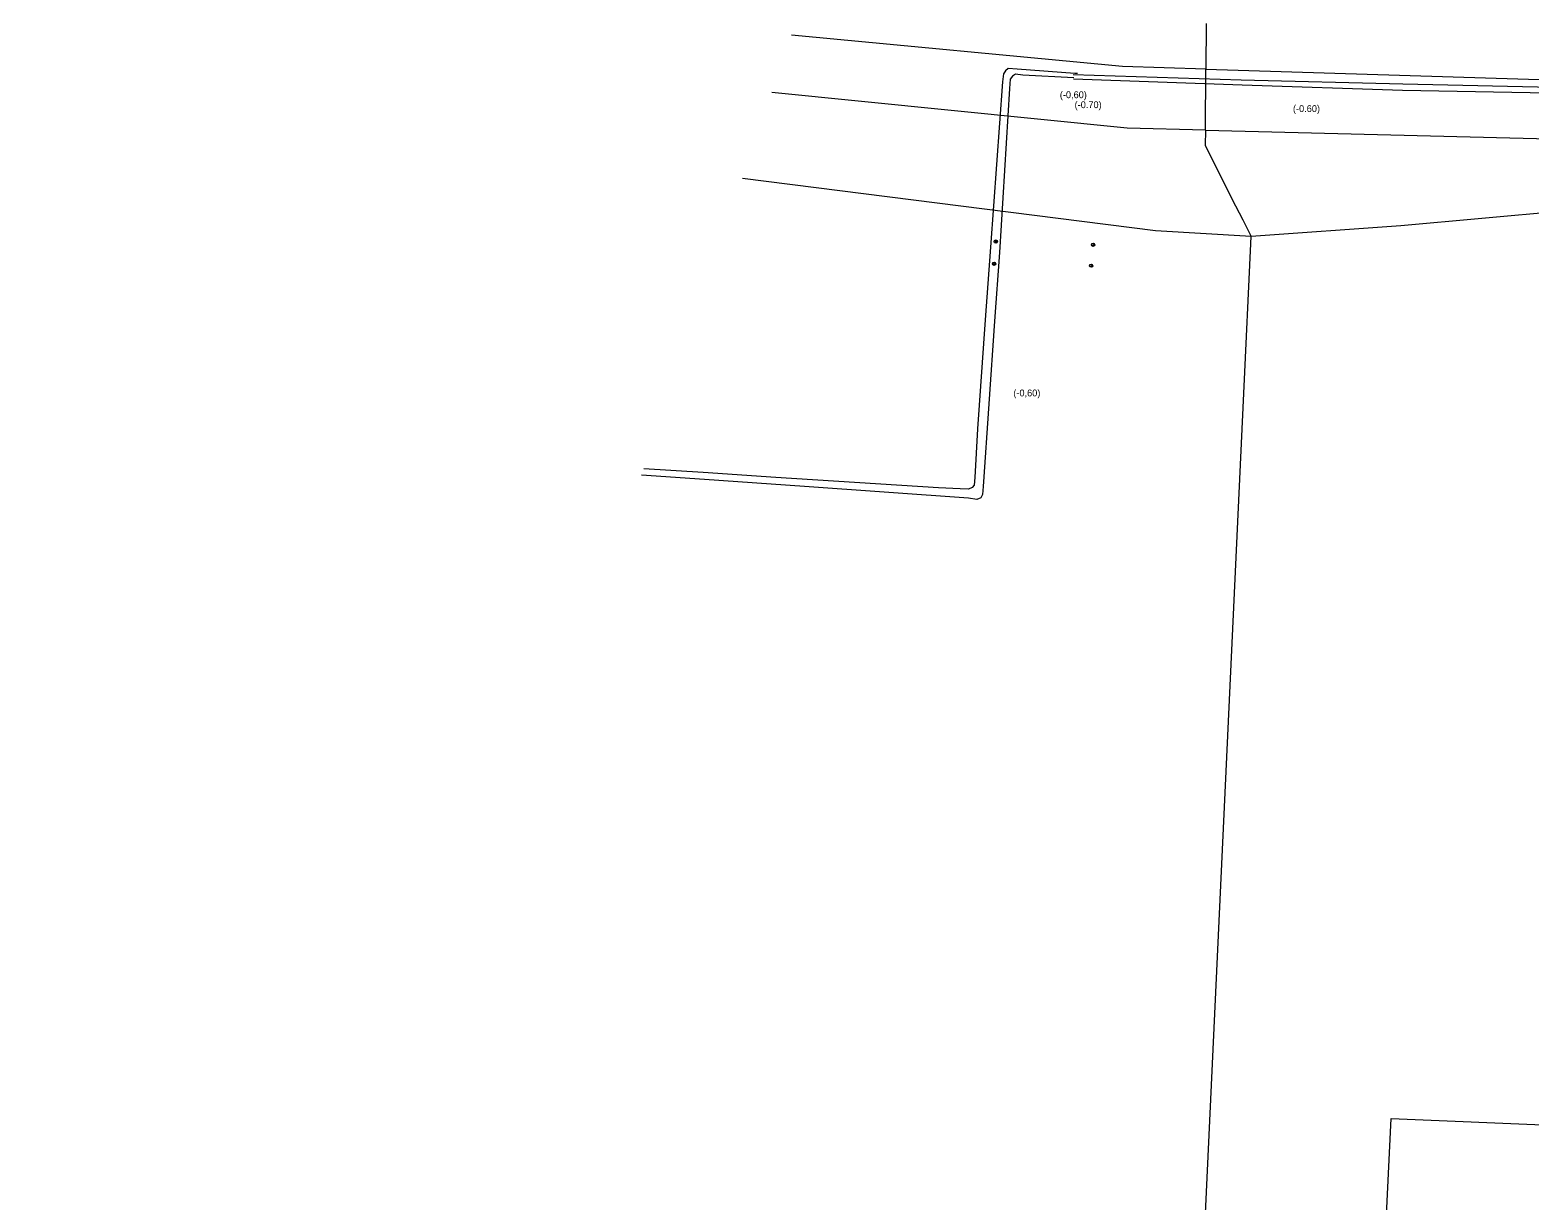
# Model space of a CAD drawing. Extents: x -725191 to -724881, y -978080 to -977718.
# Drawn here: x -725190.7 to -725081.4, y -977926.4 to -977841.1 of the extents above; entities that cross this region are included whole.
import ezdxf
from ezdxf.enums import TextEntityAlignment as Align

# ---------------------------------------------------------------- set-up
doc = ezdxf.new("R2010")
doc.units = 0
doc.header["$LTSCALE"] = 0.48
doc.header["$PDMODE"] = 32
doc.header["$PDSIZE"] = 0.24
for name, color, linetype, lineweight in [('1', 7, 'Continuous', 13), ('46', 7, 'Continuous', 13), ('48', 7, 'Continuous', 13), ('63', 7, 'Continuous', 13)]:
    doc.layers.add(name, color=color, linetype=linetype, lineweight=lineweight)

msp = doc.modelspace()

# ---------------------------------------------------------------- linework, layer by layer
at = {"layer": '1'}
for p, q in [((-725105.04, -977840.64), (-725105.06, -977843.95)), ((-725105.09, -977848.39), (-725105.06, -977843.95)), ((-725105.09, -977848.39), (-725105.1, -977849.52)), ((-725055.84, -977852.15), (-725090.85, -977855.37)), ((-725090.85, -977855.37), (-725101.75, -977856.14))]:
    msp.add_line(p, q, dxfattribs=at)
for points in [[(-725105.06, -977843.95), (-725111.12, -977843.76), (-725135.244, -977841.492)], [(-725105.06, -977843.95), (-725052.58, -977845.59), (-725051.57, -977845.62), (-725031.66, -977846.24)], [(-725105.09, -977848.39), (-725110.79, -977848.25), (-725136.664, -977845.661)], [(-725105.09, -977848.39), (-725053.02, -977849.71), (-725052.02, -977849.73), (-725031.28, -977850.26)], [(-725105.1, -977849.52), (-725102.89, -977853.9), (-725102.36, -977854.94), (-725101.75, -977856.14)], [(-725101.75, -977856.14), (-725108.73, -977855.73), (-725138.797, -977851.924)], [(-725190.701, -978004.31), (-725109.15, -978014), (-725101.75, -977856.14)], [(-725035.36, -977935.22), (-725043.75, -977934.93), (-725044.06, -977940.9), (-725092.45, -977938.91), (-725091.57, -977920.38), (-725042.12, -977922.44)]]:
    msp.add_lwpolyline(points, dxfattribs=at)
at = {"layer": '48'}
for points in [[(-725120.36, -977856.548), (-725120.381, -977856.509), (-725120.357, -977856.473), (-725120.312, -977856.474), (-725120.291, -977856.512), (-725120.315, -977856.549)], [(-725120.5, -977858.167), (-725120.522, -977858.129), (-725120.499, -977858.092), (-725120.454, -977858.093), (-725120.432, -977858.131), (-725120.455, -977858.168)]]:
    msp.add_lwpolyline(points, close=True, dxfattribs=at)
for p in [(-725120.36, -977856.51), (-725113.271, -977856.742), (-725120.48, -977858.13), (-725113.417, -977858.267)]:
    msp.add_point(p, dxfattribs=at)
at = {"layer": '63'}
msp.add_line((-725114.417, -977844.281), (-725114.61, -977844.27), dxfattribs=at)
for points in [[(-724996.78, -977832.3), (-724997.07, -977844.29), (-724997.12, -977846.74), (-724997.13, -977847.34), (-724997.28, -977847.6), (-724997.53, -977847.71), (-724998.14, -977847.69), (-725010.12, -977847.35), (-725022.19, -977846.94), (-725034.17, -977846.58), (-725046.16, -977846.17), (-725052.297, -977846.041), (-725054.5, -977845.99), (-725056.407, -977845.955), (-725066.64, -977845.74), (-725078.71, -977845.31), (-725090.71, -977845.05), (-725102.48, -977844.75), (-725114.72, -977844.37)], [(-725114.7, -977844.66), (-725102.42, -977845.11), (-725090.73, -977845.48), (-725078.78, -977845.7), (-725066.72, -977846.15), (-725056.681, -977846.35), (-725054.7, -977846.39), (-725052.296, -977846.437), (-725045.64, -977846.57), (-725033.74, -977847.05), (-725021.75, -977847.47), (-725009.76, -977847.84), (-724997.78, -977848.14), (-724997.15, -977848.14), (-724996.88, -977847.98), (-724996.72, -977847.77), (-724996.68, -977847.12), (-724996.65, -977844.4), (-724996.35, -977832.44)], [(-725114.61, -977844.27), (-725118.8, -977843.96), (-725119.46, -977843.92), (-725119.65, -977844.07), (-725119.79, -977844.29), (-725119.88, -977844.88), (-725120.75, -977856.91), (-725121.13, -977862.22), (-725121.69, -977870.14), (-725121.89, -977873.69), (-725121.93, -977874.24), (-725122.08, -977874.43), (-725122.34, -977874.54), (-725122.95, -977874.51), (-725124.53, -977874.44), (-725136.39, -977873.69), (-725141.66, -977873.33), (-725145.994, -977873.052)], [(-725114.67, -977844.6), (-725118.38, -977844.39), (-725118.92, -977844.33), (-725119.14, -977844.46), (-725119.3, -977844.68), (-725119.36, -977845.36), (-725120.08, -977857.32), (-725120.46, -977862.31), (-725121.28, -977874.34), (-725121.33, -977874.92), (-725121.45, -977875.18), (-725121.73, -977875.29), (-725122.35, -977875.2), (-725134.3, -977874.35), (-725141.58, -977873.83), (-725146.154, -977873.524)]]:
    msp.add_lwpolyline(points, dxfattribs=at)

# ---------------------------------------------------------------- texts
at = {"layer": '46'}
for s, p in [('(-0,60)', (-725114.71, -977846.071)), ('(-0.70)', (-725113.633, -977846.797)), ('(-0.60)', (-725097.729, -977847.079)), ('(-0,60)', (-725118.0955, -977867.787))]:
    msp.add_text(s, height=0.5, dxfattribs=at).set_placement(p, align=Align.CENTER)

doc.saveas('drawing.dxf')
